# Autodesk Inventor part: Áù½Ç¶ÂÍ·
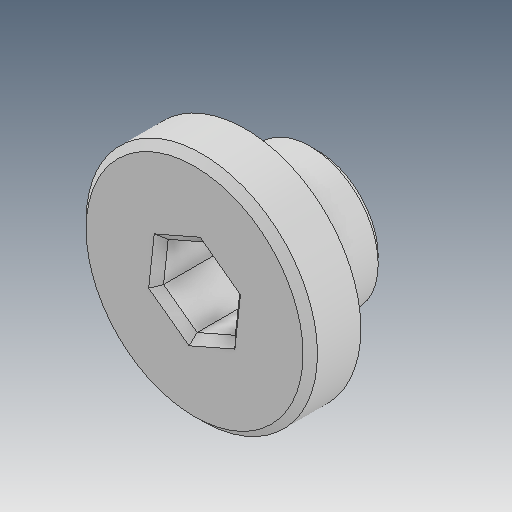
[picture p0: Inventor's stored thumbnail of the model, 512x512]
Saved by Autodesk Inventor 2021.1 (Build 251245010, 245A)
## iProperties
Created: 2019-04
Part Number: Áù½Ç¶ÂÍ·
Material: Ogólny
Document SubType Name: Modeling
Designer: user
Density: 1 g/cm^3
Appearance: Domyślna
Author: user
Revision Number: ÈÎºÎ
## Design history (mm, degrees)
feature "ÊäÈë1"
node "Bryła1"
